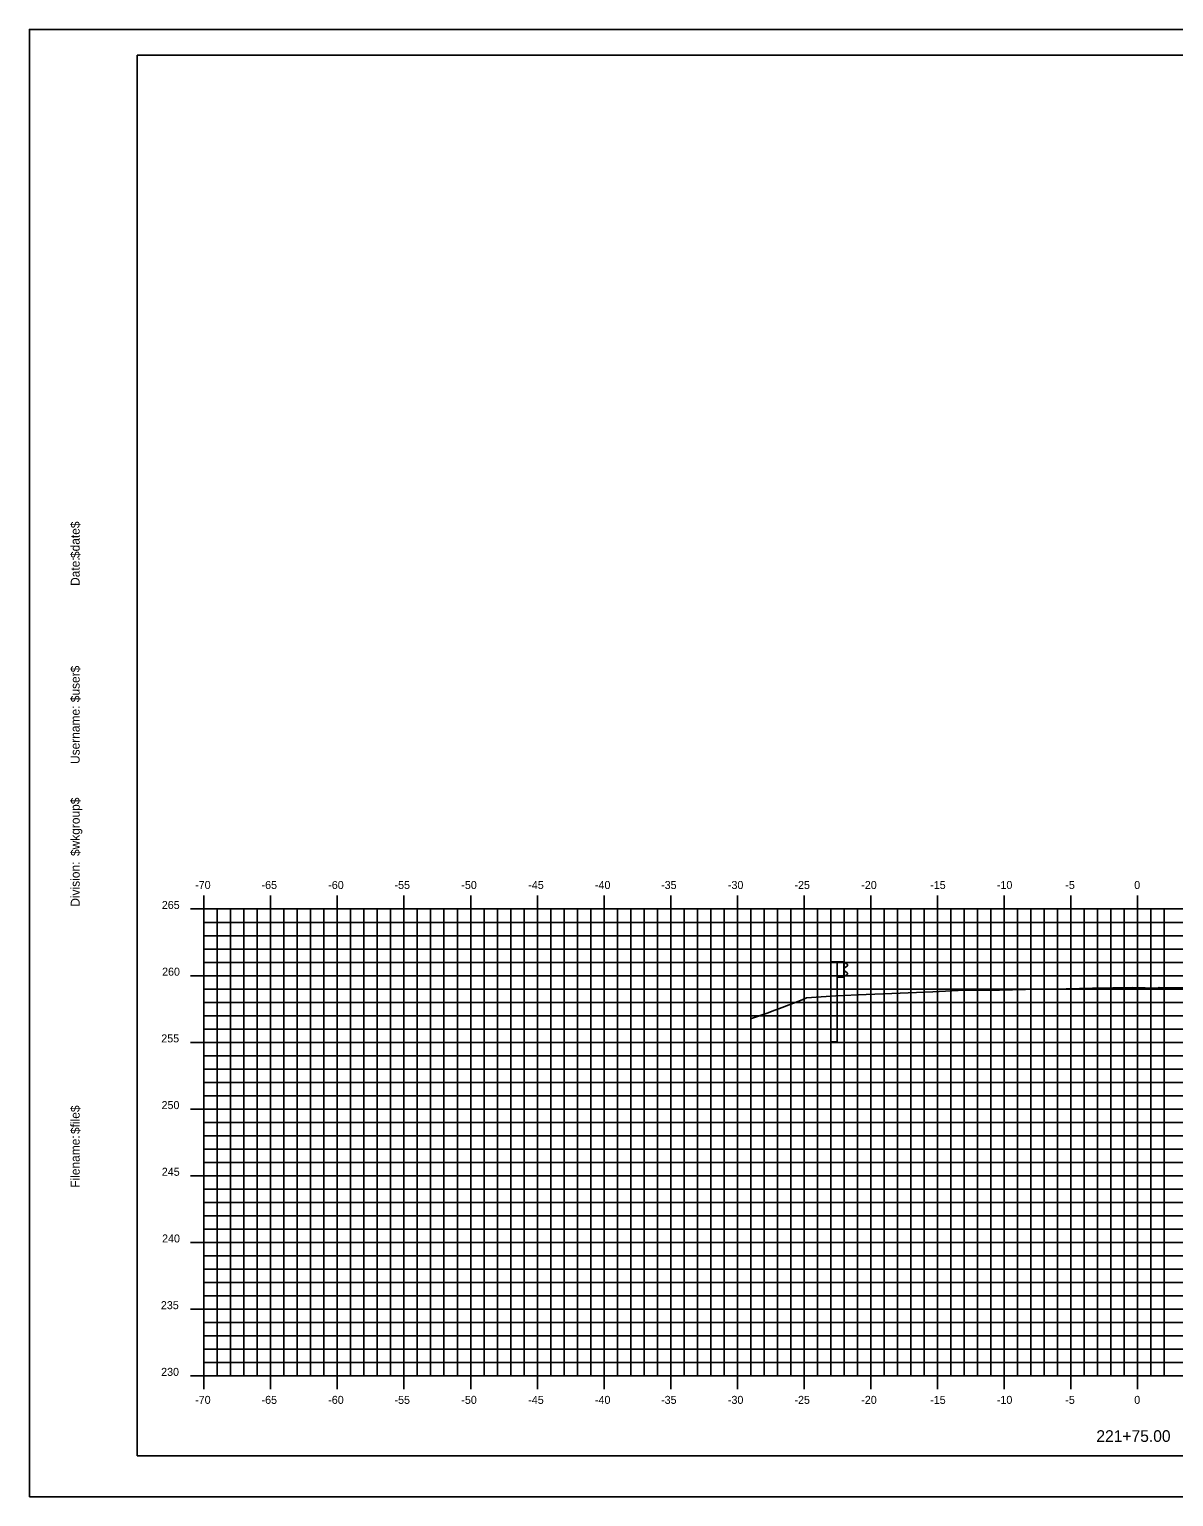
# Model space of a CAD drawing. Extents: x -22 to 1480, y -1511 to 8.
# Drawn here: x 1308.4 to 1394.2, y -184.5 to -74.5 of the extents above; entities that cross this region are included whole.
import ezdxf

# ---------------------------------------------------------------- set-up
doc = ezdxf.new("R2010")
doc.units = 0
for name, color, linetype in [('BORDER', 7, 'Continuous'), ('H_V ANNOTATION', 7, 'Continuous'), ('MAJOR', 7, 'Continuous'), ('MINOR', 7, 'Continuous'), ('PLOT BOUNDARY', 7, 'Continuous'), ('S_Guardrail_Beam', 7, 'Continuous'), ('S_Roadway_Centerline', 7, 'Continuous')]:
    doc.layers.add(name, color=color, linetype=linetype)

msp = doc.modelspace()

# ---------------------------------------------------------------- linework, layer by layer
at = {"layer": 'BORDER'}
for p, q in [((1476.48, -76.47), (1316.48, -76.47)), ((1316.48, -76.47), (1316.48, -181.47)), ((1316.48, -181.47), (1476.48, -181.47))]:
    msp.add_line(p, q, dxfattribs=at)
at = {"layer": 'MAJOR'}
for p, q in [((1321.48, -139.46), (1321.48, -140.47)), ((1326.48, -139.46), (1326.48, -140.47)), ((1331.48, -139.46), (1331.48, -140.47)), ((1336.48, -139.46), (1336.48, -140.47)), ((1341.48, -139.46), (1341.48, -140.47)), ((1346.48, -139.46), (1346.48, -140.47)), ((1351.48, -139.46), (1351.48, -140.47)), ((1356.48, -139.46), (1356.48, -140.47)), ((1361.48, -139.46), (1361.48, -140.47)), ((1366.48, -139.46), (1366.48, -140.47)), ((1371.48, -139.46), (1371.48, -140.47)), ((1376.48, -139.46), (1376.48, -140.47)), ((1381.48, -139.46), (1381.48, -140.47)), ((1386.48, -139.46), (1386.48, -140.47)), ((1391.48, -139.46), (1391.48, -140.47)), ((1320.48, -140.47), (1321.48, -140.47)), ((1321.48, -140.47), (1461.48, -140.47)), ((1321.48, -175.47), (1321.48, -140.47)), ((1321.48, -175.47), (1321.48, -140.47)), ((1321.48, -140.47), (1461.48, -140.47)), ((1326.48, -175.47), (1326.48, -140.47)), ((1331.48, -175.47), (1331.48, -140.47)), ((1336.48, -175.47), (1336.48, -140.47)), ((1341.48, -175.47), (1341.48, -140.47)), ((1346.48, -175.47), (1346.48, -140.47)), ((1351.48, -175.47), (1351.48, -140.47)), ((1356.48, -175.47), (1356.48, -140.47)), ((1361.48, -175.47), (1361.48, -140.47)), ((1366.48, -175.47), (1366.48, -140.47)), ((1371.48, -175.47), (1371.48, -140.47)), ((1376.48, -175.47), (1376.48, -140.47)), ((1381.48, -175.47), (1381.48, -140.47)), ((1386.48, -175.47), (1386.48, -140.47)), ((1391.48, -175.47), (1391.48, -140.47)), ((1320.48, -145.47), (1321.48, -145.47)), ((1321.48, -145.47), (1461.48, -145.47)), ((1320.48, -150.47), (1321.48, -150.47)), ((1321.48, -150.47), (1461.48, -150.47)), ((1320.48, -155.47), (1321.48, -155.47)), ((1321.48, -155.47), (1461.48, -155.47)), ((1320.48, -160.47), (1321.48, -160.47)), ((1321.48, -160.47), (1461.48, -160.47)), ((1320.48, -165.47), (1321.48, -165.47)), ((1321.48, -165.47), (1461.48, -165.47)), ((1320.48, -170.47), (1321.48, -170.47)), ((1321.48, -170.47), (1461.48, -170.47)), ((1320.48, -175.47), (1321.48, -175.47)), ((1321.48, -175.47), (1461.48, -175.47)), ((1321.48, -175.47), (1461.48, -175.47)), ((1321.48, -176.47), (1321.48, -175.47)), ((1326.48, -176.47), (1326.48, -175.47)), ((1331.48, -176.47), (1331.48, -175.47)), ((1336.48, -176.47), (1336.48, -175.47)), ((1341.48, -176.47), (1341.48, -175.47)), ((1346.48, -176.47), (1346.48, -175.47)), ((1351.48, -176.47), (1351.48, -175.47)), ((1356.48, -176.47), (1356.48, -175.47)), ((1361.48, -176.47), (1361.48, -175.47)), ((1366.48, -176.47), (1366.48, -175.47)), ((1371.48, -176.47), (1371.48, -175.47)), ((1376.48, -176.47), (1376.48, -175.47)), ((1381.48, -176.47), (1381.48, -175.47)), ((1386.48, -176.47), (1386.48, -175.47)), ((1391.48, -176.47), (1391.48, -175.47))]:
    msp.add_line(p, q, dxfattribs=at)
at = {"layer": 'MINOR'}
for p, q in [((1322.48, -175.47), (1322.48, -140.47)), ((1323.48, -175.47), (1323.48, -140.47)), ((1324.48, -175.47), (1324.48, -140.47)), ((1325.48, -175.47), (1325.48, -140.47)), ((1327.48, -175.47), (1327.48, -140.47)), ((1328.48, -175.47), (1328.48, -140.47)), ((1329.48, -175.47), (1329.48, -140.47)), ((1330.48, -175.47), (1330.48, -140.47)), ((1332.48, -175.47), (1332.48, -140.47)), ((1333.48, -175.47), (1333.48, -140.47)), ((1334.48, -175.47), (1334.48, -140.47)), ((1335.48, -175.47), (1335.48, -140.47)), ((1337.48, -175.47), (1337.48, -140.47)), ((1338.48, -175.47), (1338.48, -140.47)), ((1339.48, -175.47), (1339.48, -140.47)), ((1340.48, -175.47), (1340.48, -140.47)), ((1342.48, -175.47), (1342.48, -140.47)), ((1343.48, -175.47), (1343.48, -140.47)), ((1344.48, -175.47), (1344.48, -140.47)), ((1345.48, -175.47), (1345.48, -140.47)), ((1347.48, -175.47), (1347.48, -140.47)), ((1348.48, -175.47), (1348.48, -140.47)), ((1349.48, -175.47), (1349.48, -140.47)), ((1350.48, -175.47), (1350.48, -140.47)), ((1352.48, -175.47), (1352.48, -140.47)), ((1353.48, -175.47), (1353.48, -140.47)), ((1354.48, -175.47), (1354.48, -140.47)), ((1355.48, -175.47), (1355.48, -140.47)), ((1357.48, -175.47), (1357.48, -140.47)), ((1358.48, -175.47), (1358.48, -140.47)), ((1359.48, -175.47), (1359.48, -140.47)), ((1360.48, -175.47), (1360.48, -140.47)), ((1362.48, -175.47), (1362.48, -140.47)), ((1363.48, -175.47), (1363.48, -140.47)), ((1364.48, -175.47), (1364.48, -140.47)), ((1365.48, -175.47), (1365.48, -140.47)), ((1367.48, -175.47), (1367.48, -140.47)), ((1368.48, -175.47), (1368.48, -140.47)), ((1369.48, -175.47), (1369.48, -140.47)), ((1370.48, -175.47), (1370.48, -140.47)), ((1372.48, -175.47), (1372.48, -140.47)), ((1373.48, -175.47), (1373.48, -140.47)), ((1374.48, -175.47), (1374.48, -140.47)), ((1375.48, -175.47), (1375.48, -140.47)), ((1377.48, -175.47), (1377.48, -140.47)), ((1378.48, -175.47), (1378.48, -140.47)), ((1379.48, -175.47), (1379.48, -140.47)), ((1380.48, -175.47), (1380.48, -140.47)), ((1382.48, -175.47), (1382.48, -140.47)), ((1383.48, -175.47), (1383.48, -140.47)), ((1384.48, -175.47), (1384.48, -140.47)), ((1385.48, -175.47), (1385.48, -140.47)), ((1387.48, -175.47), (1387.48, -140.47)), ((1388.48, -175.47), (1388.48, -140.47)), ((1389.48, -175.47), (1389.48, -140.47)), ((1390.48, -175.47), (1390.48, -140.47)), ((1392.48, -175.47), (1392.48, -140.47)), ((1393.48, -175.47), (1393.48, -140.47)), ((1321.48, -141.47), (1461.48, -141.47)), ((1321.48, -141.47), (1322.48, -141.47)), ((1321.48, -142.47), (1461.48, -142.47)), ((1321.48, -142.47), (1322.48, -142.47)), ((1321.48, -143.47), (1461.48, -143.47)), ((1321.48, -143.47), (1322.48, -143.47)), ((1321.48, -144.47), (1461.48, -144.47)), ((1321.48, -144.47), (1322.48, -144.47)), ((1321.48, -146.47), (1461.48, -146.47)), ((1321.48, -146.47), (1322.48, -146.47)), ((1321.48, -147.47), (1461.48, -147.47)), ((1321.48, -147.47), (1322.48, -147.47)), ((1321.48, -148.47), (1461.48, -148.47)), ((1321.48, -148.47), (1322.48, -148.47)), ((1321.48, -149.47), (1461.48, -149.47)), ((1321.48, -149.47), (1322.48, -149.47)), ((1321.48, -151.47), (1461.48, -151.47)), ((1321.48, -151.47), (1322.48, -151.47)), ((1321.48, -152.47), (1461.48, -152.47)), ((1321.48, -152.47), (1322.48, -152.47)), ((1321.48, -153.47), (1461.48, -153.47)), ((1321.48, -153.47), (1322.48, -153.47)), ((1321.48, -154.47), (1461.48, -154.47)), ((1321.48, -154.47), (1322.48, -154.47)), ((1321.48, -156.47), (1461.48, -156.47)), ((1321.48, -156.47), (1322.48, -156.47)), ((1321.48, -157.47), (1461.48, -157.47)), ((1321.48, -157.47), (1322.48, -157.47)), ((1321.48, -158.47), (1461.48, -158.47)), ((1321.48, -158.47), (1322.48, -158.47)), ((1321.48, -159.47), (1461.48, -159.47)), ((1321.48, -159.47), (1322.48, -159.47)), ((1321.48, -161.47), (1461.48, -161.47)), ((1321.48, -161.47), (1322.48, -161.47)), ((1321.48, -162.47), (1461.48, -162.47)), ((1321.48, -162.47), (1322.48, -162.47)), ((1321.48, -163.47), (1461.48, -163.47)), ((1321.48, -163.47), (1322.48, -163.47)), ((1321.48, -164.47), (1461.48, -164.47)), ((1321.48, -164.47), (1322.48, -164.47)), ((1321.48, -166.47), (1461.48, -166.47)), ((1321.48, -166.47), (1322.48, -166.47)), ((1321.48, -167.47), (1461.48, -167.47)), ((1321.48, -167.47), (1322.48, -167.47)), ((1321.48, -168.47), (1461.48, -168.47)), ((1321.48, -168.47), (1322.48, -168.47)), ((1321.48, -169.47), (1461.48, -169.47)), ((1321.48, -169.47), (1322.48, -169.47)), ((1321.48, -171.47), (1461.48, -171.47)), ((1321.48, -171.47), (1322.48, -171.47)), ((1321.48, -172.47), (1461.48, -172.47)), ((1321.48, -172.47), (1322.48, -172.47)), ((1321.48, -173.47), (1461.48, -173.47)), ((1321.48, -173.47), (1322.48, -173.47)), ((1321.48, -174.47), (1461.48, -174.47)), ((1321.48, -174.47), (1322.48, -174.47))]:
    msp.add_line(p, q, dxfattribs=at)
at = {"layer": 'PLOT BOUNDARY'}
msp.add_lwpolyline([(1308.39, -184.53), (1478.39, -184.53), (1478.39, -74.53), (1308.39, -74.53)], close=True, dxfattribs=at)
at = {"layer": 'S_Guardrail_Beam'}
for p, q in [((1368.48, -144.42), (1368.48, -150.42)), ((1368.97, -144.42), (1368.48, -144.42)), ((1369.46, -144.42), (1368.97, -144.42)), ((1368.97, -144.42), (1368.97, -145.58)), ((1369.46, -145.58), (1369.46, -144.42)), ((1369.46, -144.49), (1369.55, -144.5)), ((1369.48, -144.95), (1369.48, -145.05)), ((1369.71, -144.75), (1369.51, -144.89)), ((1369.51, -145.11), (1369.71, -145.25)), ((1369.56, -144.51), (1369.71, -144.61)), ((1368.97, -150.42), (1368.97, -145.58)), ((1368.97, -145.58), (1369.46, -145.58)), ((1369.55, -145.5), (1369.46, -145.51)), ((1369.71, -145.39), (1369.56, -145.49)), ((1368.97, -150.42), (1368.48, -150.42))]:
    msp.add_line(p, q, dxfattribs=at)
for centre, major_axis, start_param, end_param in [((1369.56, -144.95), (-0.0789, 0), 5.323254, 6.283185), ((1369.56, -145.05), (-0.0789, 0), 6.283185, 7.243116), ((1369.54, -144.54), (0.0417, 0), 0.959931, 1.396263), ((1369.66, -144.68), (0.0877, 0), 5.323254, 7.243116), ((1369.54, -145.45), (0.0417, 0), 4.886922, 5.323254), ((1369.66, -145.32), (0.0877, 0), 5.323254, 7.243116)]:
    msp.add_ellipse(centre, major_axis=major_axis, ratio=0.995501, start_param=start_param, end_param=end_param, dxfattribs=at)
at = {"layer": 'S_Roadway_Centerline'}
msp.add_lwpolyline([(1362.53, -148.67), (1363.71, -148.27), (1364.28, -148.06), (1364.51, -147.98), (1366.35, -147.28), (1366.66, -147.14), (1368.87, -146.99), (1371.13, -146.88), (1373.07, -146.8), (1376.13, -146.67), (1378.03, -146.59), (1379.98, -146.55), (1381.13, -146.55), (1383.09, -146.51), (1386.13, -146.45), (1388.1, -146.41), (1391.13, -146.36), (1393.02, -146.4), (1393.11, -146.35), (1396.13, -146.38)], dxfattribs=at)

# ---------------------------------------------------------------- texts
at = {"layer": 'BORDER'}
for s, p in [('$date$', (1312.16, -114.16)), ('Date:', (1312.16, -116.25)), ('$user$', (1312.16, -124.97)), ('Username:', (1312.16, -129.6)), ('$wkgroup$', (1312.16, -136.5)), ('Division:', (1312.16, -140.3)), ('$file$', (1312.16, -157.34)), ('Filename:', (1312.16, -161.37))]:
    msp.add_text(s, height=0.67, rotation=90, dxfattribs=at).set_placement(p)
at = {"layer": 'H_V ANNOTATION'}
for s, height, p in [('-70', 0.6, (1320.82, -138.97)), ('-65', 0.6, (1325.8, -138.97)), ('-60', 0.6, (1330.8, -138.97)), ('-55', 0.6, (1335.77, -138.97)), ('-50', 0.6, (1340.78, -138.97)), ('-45', 0.6, (1345.8, -138.97)), ('-40', 0.6, (1350.8, -138.97)), ('-35', 0.6, (1355.76, -138.97)), ('-30', 0.6, (1360.77, -138.97)), ('-25', 0.6, (1365.76, -138.97)), ('-20', 0.6, (1370.77, -138.97)), ('-15', 0.6, (1375.94, -138.97)), ('-10', 0.6, (1380.94, -138.97)), ('-5', 0.6, (1386.07, -138.97)), ('0', 0.6, (1391.24, -138.97)), ('265', 0.6, (1318.32, -140.47)), ('260', 0.6, (1318.34, -145.47)), ('255', 0.6, (1318.28, -150.47)), ('250', 0.6, (1318.3, -155.47)), ('245', 0.6, (1318.32, -160.47)), ('240', 0.6, (1318.34, -165.47)), ('235', 0.6, (1318.25, -170.47)), ('230', 0.6, (1318.27, -175.47)), ('-70', 0.6, (1320.82, -177.57)), ('-65', 0.6, (1325.8, -177.57)), ('-60', 0.6, (1330.8, -177.57)), ('-55', 0.6, (1335.77, -177.57)), ('-50', 0.6, (1340.78, -177.57)), ('-45', 0.6, (1345.8, -177.57)), ('-40', 0.6, (1350.8, -177.57)), ('-35', 0.6, (1355.76, -177.57)), ('-30', 0.6, (1360.77, -177.57)), ('-25', 0.6, (1365.76, -177.57)), ('-20', 0.6, (1370.77, -177.57)), ('-15', 0.6, (1375.94, -177.57)), ('-10', 0.6, (1380.94, -177.57)), ('-5', 0.6, (1386.07, -177.57)), ('0', 0.6, (1391.24, -177.57)), ('221+75.00', 0.875, (1388.4, -180.42))]:
    msp.add_text(s, height=height, dxfattribs=at).set_placement(p)

doc.saveas('drawing.dxf')
